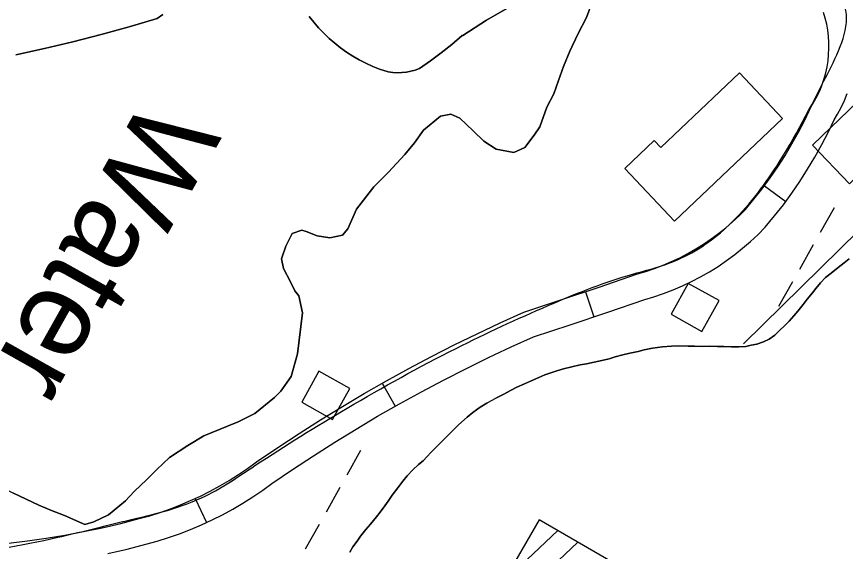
# Model space of a CAD drawing. Extents: x 3913936 to 3933962, y 195330 to 217741.
# Drawn here: x 3929093.3 to 3929562.5, y 208791.7 to 209094.2 of the extents above; entities that cross this region are included whole.
import ezdxf

# ---------------------------------------------------------------- set-up
doc = ezdxf.new("R2010")
doc.units = 0
for name, color, linetype in [('V-BLDG-OTLN', 7, 'Continuous'), ('V-DOMW-TANK', 7, 'Continuous'), ('V-RIVR-IDEN', 7, 'Continuous'), ('V-ROAD-CNTR', 7, 'Continuous'), ('V-TOPO-SHOR', 7, 'Continuous'), ('V-WETL-SWMP', 7, 'Continuous')]:
    doc.layers.add(name, color=color, linetype=linetype)

msp = doc.modelspace()

# ---------------------------------------------------------------- linework, layer by layer
at = {"layer": 'V-BLDG-OTLN'}
for points in [[(3929465.83, 208978.61), (3929526.94, 209036.57), (3929502.49, 209062.35), (3929458.07, 209020.22), (3929454.31, 209024.18), (3929437.62, 209008.35)], [(3929564.88, 208999.69), (3929605.77, 209039.09), (3929584.78, 209060.87), (3929543.9, 209021.47)], [(3929473.52, 208943.31), (3929463.8, 208925.83), (3929481.29, 208916.12), (3929491, 208933.6)], [(3929264.47, 208893.59), (3929254.75, 208876.11), (3929272.24, 208866.4), (3929281.95, 208883.88)]]:
    msp.add_lwpolyline(points, close=True, dxfattribs=at)
for points in [[(3929494.11, 208748.93), (3929389.15, 208809.62), (3929312.18, 208676.5)], [(3929368.48, 208773.87), (3929399.69, 208803.53)], [(3929346.35, 208735.6), (3929410.97, 208797.01)]]:
    msp.add_lwpolyline(points, dxfattribs=at)
at = {"layer": 'V-DOMW-TANK'}
msp.add_lwpolyline([(3929504.81, 208909.13), (3929581.05, 208983.89), (3929576.87, 208997.02)], dxfattribs=at)
at = {"layer": 'V-ROAD-CNTR'}
for p, q in [((3929516.66, 208998.55), (3929528.77, 208989.69)), ((3929415.31, 208938.6), (3929420.1, 208924.38)), ((3929300.27, 208886.85), (3929307.7, 208873.82)), ((3929194.51, 208821.65), (3929200.8, 208808.03))]:
    msp.add_line(p, q, dxfattribs=at)
for points in [[(3929088.78, 208796.38), (3929099.46, 208797.66), (3929110.1, 208799.18), (3929120.71, 208800.93), (3929131.28, 208802.91), (3929141.81, 208805.12), (3929152.28, 208807.56), (3929162.7, 208810.24), (3929168.69, 208811.9), (3929174.58, 208813.75), (3929180.4, 208815.79), (3929186.16, 208818.01), (3929191.84, 208820.42), (3929197.45, 208823.01), (3929202.96, 208825.78), (3929208.39, 208828.72), (3929213.71, 208831.84), (3929218.94, 208835.13), (3929224.05, 208838.59), (3929229.23, 208842.34), (3929241.2, 208850.5), (3929253.26, 208858.44), (3929265.45, 208866.19), (3929277.75, 208873.74), (3929290.18, 208881.09), (3929302.72, 208888.25), (3929315.38, 208895.2), (3929328.14, 208901.95), (3929341.01, 208908.5), (3929353.99, 208914.84), (3929367.06, 208920.97), (3929380.53, 208927.03), (3929402.04, 208934.13), (3929423.12, 208941.22), (3929444.32, 208948.51), (3929449.58, 208950.07), (3929454.49, 208951.73), (3929459.33, 208953.58), (3929464.09, 208955.61), (3929468.77, 208957.83), (3929473.37, 208960.22), (3929477.86, 208962.79), (3929482.26, 208965.53), (3929486.55, 208968.43), (3929490.72, 208971.5), (3929494.77, 208974.73), (3929498.7, 208978.11), (3929502.49, 208981.64), (3929506.01, 208985.17), (3929510.75, 208990.87), (3929515.44, 208996.88), (3929519.95, 209003.03), (3929524.26, 209009.32), (3929528.37, 209015.75), (3929532.29, 209022.29), (3929536, 209028.95), (3929539.5, 209035.73), (3929543, 209043.04), (3929545.08, 209046.49), (3929546.7, 209049.55), (3929548.15, 209052.68), (3929549.43, 209055.9), (3929550.52, 209059.17), (3929551.43, 209062.51), (3929552.16, 209065.89), (3929552.7, 209069.3), (3929553.05, 209072.74), (3929553.21, 209076.2), (3929553.17, 209079.65), (3929552.95, 209083.1), (3929552.53, 209086.53), (3929551.93, 209089.93), (3929551.14, 209093.3), (3929550.16, 209096.61)], [(3929145.05, 208790.48), (3929155.84, 208792.99), (3929166.58, 208795.75), (3929172.95, 208797.52), (3929179.3, 208799.51), (3929185.58, 208801.71), (3929191.79, 208804.1), (3929197.92, 208806.7), (3929203.96, 208809.49), (3929209.91, 208812.48), (3929215.76, 208815.66), (3929221.5, 208819.02), (3929227.13, 208822.57), (3929232.65, 208826.29), (3929237.86, 208830.06), (3929249.55, 208838.04), (3929261.41, 208845.85), (3929273.4, 208853.47), (3929285.5, 208860.89), (3929297.72, 208868.12), (3929310.05, 208875.16), (3929322.5, 208882), (3929335.05, 208888.64), (3929347.71, 208895.08), (3929360.47, 208901.31), (3929373.32, 208907.34), (3929385.97, 208913.03), (3929406.78, 208919.9), (3929427.95, 208927.02), (3929448.89, 208934.22), (3929454.12, 208935.77), (3929459.57, 208937.62), (3929464.95, 208939.67), (3929470.24, 208941.93), (3929475.45, 208944.39), (3929480.55, 208947.05), (3929485.55, 208949.9), (3929490.44, 208952.95), (3929495.2, 208956.18), (3929499.84, 208959.59), (3929504.34, 208963.17), (3929508.71, 208966.93), (3929512.92, 208970.85), (3929517.11, 208975.07), (3929522.43, 208981.45), (3929527.41, 208987.83), (3929532.19, 208994.36), (3929536.76, 209001.04), (3929541.13, 209007.85), (3929545.28, 209014.79), (3929549.22, 209021.86), (3929552.93, 209029.05), (3929556.22, 209035.91), (3929558.13, 209039.09), (3929560.14, 209042.88), (3929561.94, 209046.77), (3929563.52, 209050.75)]]:
    msp.add_lwpolyline(points, dxfattribs=at)
msp.add_spline([(3928525.94, 208199.58), (3928663.47, 208448.7), (3928729.28, 208575.65), (3928772.51, 208644.8), (3928793.04, 208671.23), (3928813.16, 208685.99), (3928849.99, 208702.06), (3928901.39, 208723.29), (3928941.15, 208746.48), (3928980.61, 208763.64), (3929011.73, 208780.24), (3929053.09, 208788.77), (3929116.61, 208799.68), (3929152.59, 208808.41), (3929198.09, 208822), (3929228.27, 208840.26), (3929280.48, 208872.74), (3929342.15, 208906.58), (3929394.32, 208930.8), (3929439.03, 208947.65), (3929467.84, 208956.79), (3929496.68, 208976.36), (3929523.63, 209009.71), (3929552.13, 209061.34), (3929562.8, 209097.59), (3929549.93, 209122.48), (3929531.62, 209153.63), (3929490.5, 209225.48), (3929461.64, 209289.09), (3929459.62, 209329.37)], degree=3, dxfattribs=at)
at = {"layer": 'V-TOPO-SHOR'}
for points in [[(3929419.19, 209102.42), (3929416.02, 209093.71), (3929411.26, 209084.61), (3929406.51, 209074.71), (3929402.94, 209066.01), (3929400.16, 209058.09), (3929397.39, 209050.57), (3929393.42, 209043.05), (3929389.46, 209031.97), (3929386.28, 209027.22), (3929381.13, 209020.1), (3929374.79, 209017.33), (3929364.9, 209019.32), (3929357.78, 209023.68), (3929351.84, 209029.62), (3929344.32, 209036.75), (3929339.18, 209039.13), (3929333.24, 209037.95), (3929323.73, 209030.03), (3929318.58, 209022.91), (3929313.04, 209016.19), (3929303.92, 209006.29), (3929295.6, 208997.99), (3929285.7, 208985.32), (3929280.94, 208974.24), (3929277.77, 208970.68), (3929270.64, 208969.1), (3929263.52, 208970.29), (3929257.19, 208972.67)], [(3929258.92, 209094.35), (3929261.52, 209091.04), (3929264.27, 209087.86), (3929267.18, 209084.81), (3929270.23, 209081.9), (3929273.41, 209079.15), (3929276.71, 209076.55), (3929280.15, 209074.11), (3929283.69, 209071.83), (3929287.33, 209069.73), (3929291.08, 209067.8), (3929294.91, 209066.05), (3929298.81, 209064.49), (3929301.25, 209063.68), (3929303.75, 209063.08), (3929306.29, 209062.69), (3929308.85, 209062.51), (3929311.42, 209062.56), (3929313.97, 209062.82), (3929316.5, 209063.29), (3929318.97, 209063.98), (3929321.38, 209064.88), (3929327.64, 209069.23), (3929333.76, 209073.78), (3929339.73, 209078.53), (3929345.54, 209083.47), (3929345.94, 209083.46), (3929359.41, 209092.17), (3929370.89, 209098.89)], [(3929157.07, 209088.48), (3929172.94, 209093.08), (3929176.06, 209095.36)], [(3929092.95, 209072.55), (3929109.07, 209076.16), (3929125.14, 209080.03), (3929141.14, 209084.13), (3929157.07, 209088.48)], [(3929257.19, 208972.67), (3929254.81, 208973.47), (3929249.27, 208971.49), (3929245.7, 208964.37), (3929243.32, 208957.24), (3929244.5, 208951.7), (3929248.46, 208944.18), (3929250.83, 208939.03), (3929253.2, 208936.25), (3929255.17, 208926.75), (3929252.39, 208903.39), (3929248.82, 208890.73), (3929242.87, 208882.42), (3929239.31, 208878.86), (3929228.22, 208869.76), (3929218.71, 208865.01), (3929212.77, 208862.65), (3929199.31, 208857.11), (3929190.2, 208851.57), (3929179.9, 208844.85), (3929172.77, 208838.12), (3929166.83, 208832.19), (3929160.09, 208825.86), (3929157.32, 208822.7), (3929154.94, 208820.32), (3929145.44, 208812.41), (3929137.12, 208808.46), (3929131.97, 208806.88), (3929120.49, 208812.03)], [(3929564.74, 208957.25), (3929561.77, 208954.98), (3929558.4, 208952.31), (3929554.44, 208949.14), (3929551.17, 208946.57), (3929548.4, 208943.6), (3929545.82, 208940.44), (3929543.84, 208937.97), (3929540.97, 208934.4), (3929538.59, 208931.44), (3929535.62, 208927.68), (3929533.24, 208925.01), (3929530.77, 208922.04), (3929527.89, 208919.17), (3929525.62, 208916.99), (3929522.55, 208914.03), (3929519.38, 208911.85), (3929516.11, 208910.27), (3929512.35, 208908.99), (3929509.18, 208908.4), (3929506.11, 208907.71), (3929502.25, 208907.51), (3929498, 208907.51), (3929493.64, 208907.61), (3929490.18, 208907.61), (3929485.52, 208907.72), (3929481.86, 208907.62), (3929477.01, 208907.72), (3929473.55, 208907.83), (3929468.1, 208907.93), (3929464.04, 208907.83), (3929459, 208907.44), (3929453.26, 208906.65), (3929448.7, 208905.76), (3929445.14, 208904.77), (3929440.48, 208903.79)], [(3929440.48, 208903.79), (3929436.62, 208902.9), (3929432.17, 208901.71), (3929428.71, 208900.73), (3929424.65, 208899.64), (3929420.39, 208898.85), (3929415.94, 208897.87), (3929412.37, 208897.18), (3929407.72, 208896.19), (3929402.97, 208895), (3929399.21, 208893.92), (3929396.33, 208892.93), (3929392.37, 208891.55), (3929388.91, 208890.07), (3929384.35, 208888.09), (3929380.89, 208886.51), (3929376.53, 208884.53), (3929373.27, 208882.85), (3929368.81, 208880.48), (3929364.95, 208878.5), (3929362.28, 208877.12), (3929359.6, 208875.63), (3929355.84, 208873.26), (3929351.58, 208870.2), (3929348.41, 208867.62), (3929343.56, 208863.37), (3929339.79, 208859.51), (3929336.92, 208856.64), (3929333.36, 208853.18), (3929330.88, 208850.61), (3929327.81, 208847.64), (3929325.73, 208845.37), (3929323.55, 208842.9), (3929320.88, 208840.82), (3929317.61, 208837.85), (3929314.44, 208834.39), (3929312.06, 208831.42), (3929309.09, 208827.66), (3929306.02, 208823.61), (3929303.74, 208820.15), (3929301.86, 208817.47), (3929299.08, 208813.91), (3929297.1, 208811.34), (3929293.64, 208807.18), (3929291.06, 208804.02), (3929287.99, 208800.26), (3929286.11, 208797.59), (3929283.63, 208794.23), (3929282.05, 208791.35)], [(3929120.49, 208812.03), (3929113.14, 208814.89), (3929105.86, 208817.93), (3929098.67, 208821.18), (3929091.57, 208824.61)]]:
    msp.add_lwpolyline(points, dxfattribs=at)
at = {"layer": 'V-WETL-SWMP'}
for p, q in [((3929556.08, 208985.98), (3929548.24, 208972.03)), ((3929544.32, 208965.06), (3929536.48, 208951.11)), ((3929532.56, 208944.14), (3929524.72, 208930.19)), ((3929288.11, 208848.73), (3929280.27, 208834.78)), ((3929276.35, 208827.81), (3929268.51, 208813.86)), ((3929264.59, 208806.89), (3929256.75, 208792.94))]:
    msp.add_line(p, q, dxfattribs=at)
for points in [[(3929131.97, 208806.88), (3929137.12, 208808.46), (3929145.44, 208812.41), (3929154.94, 208820.32), (3929157.32, 208822.7), (3929160.09, 208825.86), (3929166.83, 208832.19), (3929172.77, 208838.12), (3929179.9, 208844.85), (3929190.2, 208851.57), (3929199.31, 208857.11), (3929212.77, 208862.64), (3929218.71, 208865.02), (3929228.21, 208869.76), (3929239.31, 208878.86), (3929242.87, 208882.42), (3929248.82, 208890.73), (3929252.39, 208903.4), (3929255.17, 208926.75), (3929253.2, 208936.25), (3929250.83, 208939.03), (3929248.46, 208944.18), (3929244.5, 208951.7), (3929243.32, 208957.24), (3929245.7, 208964.37), (3929249.27, 208971.49), (3929254.81, 208973.47), (3929257.18, 208972.67), (3929263.52, 208970.29), (3929270.64, 208969.1), (3929277.77, 208970.68), (3929280.94, 208974.24), (3929285.7, 208985.32), (3929295.6, 208997.99), (3929303.92, 209006.29), (3929313.04, 209016.18), (3929318.58, 209022.91), (3929323.73, 209030.03), (3929333.24, 209037.95), (3929339.18, 209039.13), (3929344.32, 209036.75), (3929351.84, 209029.62), (3929357.78, 209023.68), (3929364.9, 209019.32), (3929374.8, 209017.33), (3929381.13, 209020.1), (3929386.28, 209027.22), (3929389.45, 209031.97), (3929393.42, 209043.05), (3929397.38, 209050.57), (3929400.16, 209058.09), (3929402.94, 209066.01), (3929406.51, 209074.71), (3929411.26, 209084.61), (3929416.02, 209093.71), (3929419.19, 209102.42)], [(3929370.89, 209098.89), (3929359.41, 209092.17), (3929345.94, 209083.46), (3929345.54, 209083.47), (3929339.73, 209078.53), (3929333.76, 209073.78), (3929327.65, 209069.23), (3929321.38, 209064.88), (3929318.97, 209063.98), (3929316.5, 209063.29), (3929313.97, 209062.82), (3929311.42, 209062.56), (3929308.85, 209062.51), (3929306.29, 209062.69), (3929303.75, 209063.08), (3929301.25, 209063.68), (3929298.81, 209064.49), (3929294.91, 209066.05), (3929291.08, 209067.8), (3929287.33, 209069.73), (3929283.69, 209071.83), (3929280.14, 209074.11), (3929276.71, 209076.55), (3929273.41, 209079.15), (3929270.22, 209081.9), (3929267.18, 209084.81), (3929264.27, 209087.86), (3929261.52, 209091.04), (3929258.92, 209094.35)], [(3929176.06, 209095.36), (3929172.94, 209093.08), (3929157.07, 209088.49), (3929141.14, 209084.13), (3929125.14, 209080.02), (3929109.07, 209076.16), (3929092.95, 209072.55)], [(3929558.4, 208952.31), (3929561.77, 208954.98), (3929564.74, 208957.25)], [(3929282.04, 208791.36), (3929283.63, 208794.23), (3929286.11, 208797.59), (3929287.99, 208800.26), (3929291.06, 208804.02), (3929293.64, 208807.18), (3929297.1, 208811.34), (3929299.08, 208813.91), (3929301.86, 208817.47), (3929303.74, 208820.14), (3929306.02, 208823.61), (3929309.09, 208827.66), (3929312.06, 208831.42), (3929314.44, 208834.39), (3929317.61, 208837.85), (3929320.88, 208840.82), (3929323.55, 208842.9), (3929325.73, 208845.37), (3929327.81, 208847.64), (3929330.88, 208850.61), (3929333.36, 208853.18), (3929336.92, 208856.65), (3929339.79, 208859.51), (3929343.56, 208863.37), (3929348.41, 208867.62), (3929351.58, 208870.2), (3929355.84, 208873.26), (3929359.6, 208875.63), (3929362.27, 208877.12), (3929364.95, 208878.5), (3929368.81, 208880.48), (3929373.27, 208882.85), (3929376.53, 208884.53), (3929380.89, 208886.51), (3929384.35, 208888.09), (3929388.91, 208890.07), (3929392.37, 208891.55), (3929396.33, 208892.93), (3929399.21, 208893.92), (3929402.97, 208895), (3929407.72, 208896.19), (3929412.37, 208897.18), (3929415.94, 208897.87), (3929420.39, 208898.85), (3929424.65, 208899.64), (3929428.71, 208900.73), (3929432.17, 208901.71), (3929436.62, 208902.9), (3929440.49, 208903.79), (3929445.14, 208904.77), (3929448.7, 208905.76), (3929453.26, 208906.65), (3929459, 208907.44), (3929464.05, 208907.83), (3929468.1, 208907.93), (3929473.55, 208907.83), (3929477.01, 208907.72), (3929481.86, 208907.62), (3929485.52, 208907.72), (3929490.18, 208907.61), (3929493.64, 208907.61), (3929498, 208907.51), (3929502.25, 208907.51), (3929506.11, 208907.7), (3929509.18, 208908.4), (3929512.35, 208908.99), (3929516.11, 208910.27), (3929519.38, 208911.85), (3929522.55, 208914.03), (3929525.62, 208916.99), (3929527.89, 208919.17), (3929530.77, 208922.04), (3929533.24, 208925.01), (3929535.62, 208927.68), (3929538.59, 208931.44), (3929540.97, 208934.4), (3929543.84, 208937.97), (3929545.82, 208940.44), (3929548.4, 208943.61), (3929551.17, 208946.57), (3929554.44, 208949.14), (3929558.4, 208952.31)], [(3929044.96, 208857.24), (3929047.85, 208853.81), (3929050.92, 208850.55), (3929054.16, 208847.45), (3929057.57, 208844.54), (3929064.15, 208840.19), (3929070.85, 208836.02), (3929077.65, 208832.03), (3929084.56, 208828.23), (3929091.57, 208824.61), (3929098.67, 208821.18), (3929105.86, 208817.93), (3929113.14, 208814.89), (3929120.49, 208812.03), (3929131.97, 208806.88)]]:
    msp.add_lwpolyline(points, dxfattribs=at)

# ---------------------------------------------------------------- texts
at = {"layer": 'V-RIVR-IDEN'}
msp.add_text('Water', height=50, rotation=240.673, dxfattribs=at).set_placement((3929166.08, 209050.47))

doc.saveas('drawing.dxf')
